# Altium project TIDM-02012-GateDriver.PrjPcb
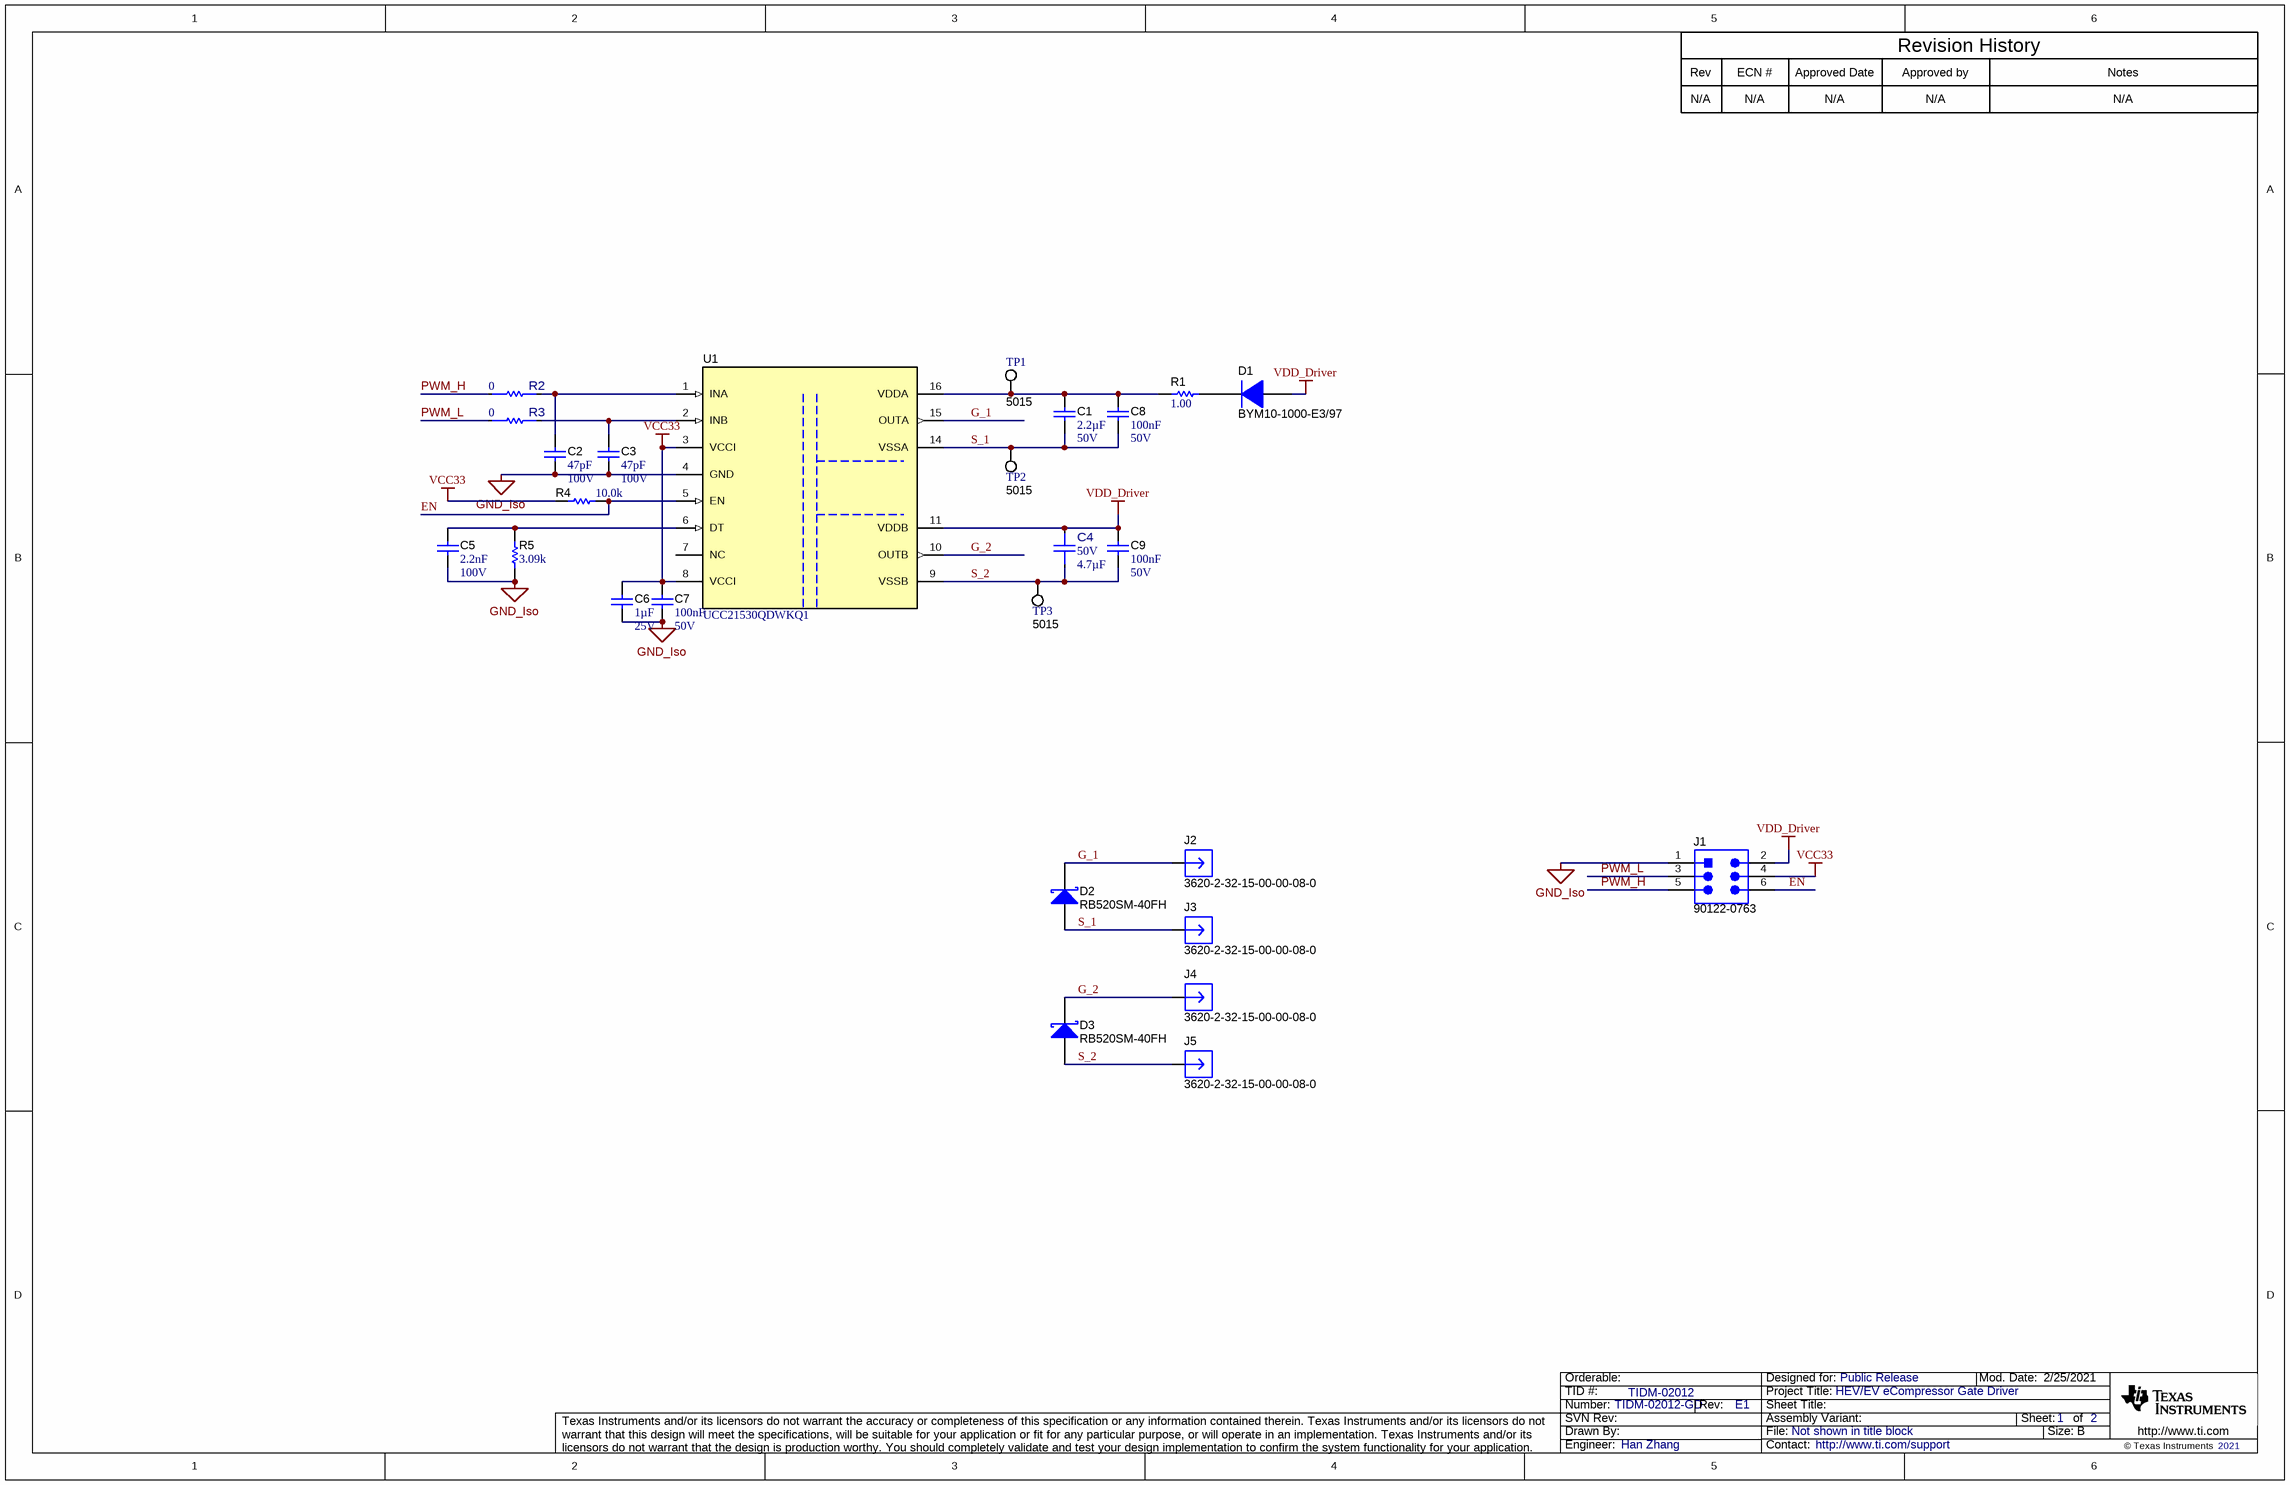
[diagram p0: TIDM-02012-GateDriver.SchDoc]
CopyrightYear: 2021; PCB_Layout: Han Zhang; PCB_Rev: E1; PRJ_Customer: Public Release; PRJ_Engineer: Han Zhang; PRJ_Number: TIDM-02012-GD; PRJ_Title: HEV/EV eCompressor Gate Driver; SCH_Rev: E1; TechSupport: http://www.ti.com/support; TID: TIDM-02012
2 sheets, 40 parts. Net scope: global (net labels, ports and power ports of the same name join across sheets).
Board file: TIDM-02012-GateDriver.PcbDoc
Sheets:
  TIDM-02012-GateDriver.SchDoc
  TIDM-02012-GateDriver_Hardware.SchDoc

## Sheet TIDM-02012-GateDriver.SchDoc
size 431 x 279 mm; Date: Not shown in title block; ApprovedBy: Not shown in title block; CheckedBy: Not shown in title block; Author: Not shown in title block; CompanyName: Not shown in title block; Engineer: Not shown in title block; Organization: Not shown in title block; Address1: Not shown in title block; Address2: Not shown in title block; Address3: Not shown in title block; Address4: Not shown in title block; DocumentNumber: 1; Revision: Use project parameter SCH_Rev; SheetNumber: 1; SheetTotal: 2; PageSetup: Record=PageOptions¦CenterHorizontal=True¦CenterVertical=True¦PrintScale=1.00¦XCorrection=1.00¦YCorrection=1.00¦PrintKind=0¦BorderSize=5000000¦LeftOffset=0¦BottomOffset=0¦Orientation=2¦PaperLength=1000¦PaperWidth=1000¦Scale=100¦PaperSource=15¦PrintQuality=600¦MediaType=1¦DitherType=10¦PaperKind=Letter¦PrintScaleMode=1

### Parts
C1  Cap_F: 2.2µF  VDC_V: 50V  [0805_HV]  (hidden comment: C2012X7R1H225M125AC)
C2  ValueDisplayed: 47pF  VDC_V: 100V  [0603]  (hidden comment: C0603C470J1GACAUTO)
C3  ValueDisplayed: 47pF  VDC_V: 100V  [0603]  (hidden comment: C0603C470J1GACAUTO)
C4  VDC_V: 50V  Cap_F: 4.7µF  [FP-C2012X7R1H475K125AC_0805-MFG]  (hidden comment: C2012X7R1H475K125AC)
C5  Cap_F: 2.2nF  VDC_V: 100V  [0603]  (hidden comment: CGA3E2X7R2A222K080AA)
C6  Cap_F: 1µF  VDC_V: 25V  [0603]  (hidden comment: CGA3E1X7R1E105M080AC)
C7  Cap_F: 100nF  VDC_V: 50V  [0603]  (hidden comment: C0603C104K5RACTU)
C8  Cap_F: 100nF  VDC_V: 50V  [0603]  (hidden comment: C0603C104K5RACTU)
C9  Cap_F: 100nF  VDC_V: 50V  [0603]  (hidden comment: C0603C104K5RACTU)
D1  BYM10-1000-E3/97  [DO-213AB]
D2  RB520SM-40FH  [SOD-523]
D3  RB520SM-40FH  [SOD-523]
J1  90122-0763  [Molex_90122-0763]
J2  3620-2-32-15-00-00-08-0  [Mill-Max_3620-2-32-xx-00-00-08-0]
J3  3620-2-32-15-00-00-08-0  [Mill-Max_3620-2-32-xx-00-00-08-0]
J4  3620-2-32-15-00-00-08-0  [Mill-Max_3620-2-32-xx-00-00-08-0]
J5  3620-2-32-15-00-00-08-0  [Mill-Max_3620-2-32-xx-00-00-08-0]
R1  ValueDisplayed: 1.00  [0805_HV]  (hidden comment: ERJ-6BQF1R0V)
R2  value 0  [FP-CRCW06030000Z0EBC_0603-MFG]  (hidden comment: CRCW06030000Z0EBC)
R3  value 0  [FP-CRCW06030000Z0EBC_0603-MFG]  (hidden comment: CRCW06030000Z0EBC)
R4  ValueDisplayed: 10.0k  [0603]  (hidden comment: RC0603FR-0710KL)
R5  ValueDisplayed: 3.09k  [0603]  (hidden comment: RC0603FR-073K09L)
TP1  5015  [Testpoint_Keystone_Miniature]
TP2  5015  [Testpoint_Keystone_Miniature]
TP3  5015  [Testpoint_Keystone_Miniature]
U1  UCC21530QDWKQ1  [DWK0014A]

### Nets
GND_Iso: C2.2 C3.2 C5.2 C6.2 C7.2 J1.1 R5.1 U1.4(GND)
VCC33: C6.1 C7.1 J1.4 R4.1 U1.3(VCCI) U1.8(VCCI)
VDD_Driver: C4.2 C9.2 D1.2(A) J1.2 U1.11(VDDB)
EN: J1.6 R4.2 U1.5(EN)
G_1: D2.1(K) J2.1 U1.15(OUTA)
G_2: D3.1(K) J4.1 U1.10(OUTB)
PWM_H: J1.5 R2.1
PWM_L: J1.3 R3.1
S_1: C1.2 C8.1 D2.2(A) J3.1 TP2.1 U1.14(VSSA)
S_2: C4.1 C9.1 D3.2(A) J5.1 TP3.1 U1.9(VSSB)
NetC1_1: C1.1 C8.2 R1.1 TP1.1 U1.16(VDDA)
NetC2_1: C2.1 R2.2 U1.1(INA)
NetC3_1: C3.1 R3.2 U1.2(INB)
NetC5_1: C5.1 R5.2 U1.6(DT)
NetD1_1: D1.1(K) R1.2

Not connected (* = marked no-connect by the designer): U1 7(NC)

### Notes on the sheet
- Rev
- N/A
- ECN #
- Approved Date
- Approved by
- Revision History
- Notes

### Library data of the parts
C1 = CMP-0007878-2: CAP, CERM, 2.2 uF, 50 V, +/- 20%, X7R, 0805; Manufacturer: TDK; TaMin_C: -55°C; Polarized: N; SizeAreaWB_mm2: 6.75; Value1: Unknown; U/M: EA; Value: 2.2uF; TaMax_C: 125°C; SizeZ_mm: 1.45; SizeX_mm: 2; SizeY_mm: 1.25; Cap_Case: 0805; SizeArea_mm2: 2.5; AEC Category: Q200
C2 C3 = CMP-0085572-1: CAP, CERM, 47 pF, 100 V,+/- 5%, C0G/NP0, AEC-Q200 Grade 1, 0603; Manufacturer: Kemet; TaMax_C: 125°C; AEC Category: Q200; AEC Grade: 1; TaMin_C: -55°C; SizeArea_mm2: 1.28; Value: 47pF; AEC Qualified: Y; Polarized: N; SizeX_mm: 1.6; U/M: EA; SizeY_mm: 0.8; SizeAreaWB_mm2: 4.68
C4 = CMP-0088943-1: 4.7µF ±10% 50V Ceramic Capacitor X7R 0805 (2012 Metric); Manufacturer: TDK; TempCo: 15%; AEC Qualified: No; ValueDisplayed: 4.7uF; SizeZ_mm: 1.5mm
C5 = CMP-0007085-4: CAP, CERM, 2200 pF, 100 V, +/- 10%, X7R, AEC-Q200 Grade 1, 0603; Manufacturer: TDK; TaMin_C: -55°C; ESR_ohm: 0.9239; Polarized: N; SizeAreaWB_mm2: 4.68; Value1: 0.923948 ohm; U/M: EA; Value: 2200pF; TaMax_C: 125°C; SizeZ_mm: 1; SizeX_mm: 1.6; SizeY_mm: 0.8; SizeArea_mm2: 1.28; AEC Qualified: Y; IRMS_A: 295.638mA; AEC Category: Q200
C6 = CMP-0082113-1: CAP, CERM, 1 µF, 25 V,+/- 20%, X7R, AEC-Q200 Grade 1, 0603; Manufacturer: TDK; SizeAreaWB_mm2: 4.68; SizeArea_mm2: 1.28; AEC Qualified: Y; AEC Category: Q200; Value: 1uF; TaMax_C: 125°C; SizeZ_mm: 1; Polarized: N; TaMin_C: -55°C; SizeY_mm: 0.8; U/M: EA; SizeX_mm: 1.6
C7-C9 = CMP-0006861-4: CAP, CERM, 0.1 uF, 50 V, +/- 10%, X7R, 0603; Manufacturer: Kemet; TaMin_C: -55°C; Polarized: N; SizeAreaWB_mm2: 4.68; Value1: Unknown; U/M: EA; Value: 0.1uF; TaMax_C: 125°C; SizeZ_mm: 1; SizeX_mm: 1.6; SizeY_mm: 0.8; SizeArea_mm2: 1.28; AEC Category: Q200
D1 = CMP-0076899-2: Diode, P-N, 1000 V, 1 A, DO-213AB; Manufacturer: Vishay-Semiconductor; Vr_V: 1kV; SizeZ_mm: 2.67; Green_REACh: Incomplete; Value: 1000V; RJC_CperW: 75.0; TJmax_C: 175°C; Green_Lifecycle: Not Set; SizeX_mm: 4.95; Io_A: 1A; SizeY_mm: 2.54; Value2: 1.2V; AEC Category: Q101; SizeAreaWB_mm2: 21.063; SizeArea_mm2: 12.573
D2 D3 = CMP-0077062-3: Diode, Schottky, 45 V, 0.2 A, AEC-Q101, SOD-523; Manufacturer: Rohm; TJmax_C: 150°C; SizeAreaWB_mm2: 5.13; Vr_V: 45V; SizeZ_mm: 0.65; SizeArea_mm2: 1.53; SizeY_mm: 0.9; Vf_V: 550mV; Value2: 0.55V; SizeX_mm: 1.7; Value: 45V; Green_REACh: Incomplete; AEC Category: Q101; Value1: 0.2A; Green_Lifecycle: Not Set; Io_A: 200mA; AEC Qualified: Y
J1 = CMP-0077741-2: Header, 2.54mm, 3x2, Gold, R/A, TH; Manufacturer: Molex; Pitch_mm: 2.54; Gender: Male; Cert_UL: Y; Current_A: 3A; Voltage_V: 350V; Shrouded: N; Row_Count: 2
J2-J5 = CMP-0055044-1: Manufacturer: Mill-Max; CNHeader: FALSE; Gender: Male; CompType: PCB Pin; Row_Count: 1; ContactFinish: Gold
R1 = CMP-0074786-1: RES, 1.00, 1%, 0.333 W, AEC-Q200 Grade 1, 0805; Manufacturer: Panasonic; Power_W: 333mW; TempCo: 200 ppm/C; Value_Code: 1R00; U/M: EA; Value: 1.00; EIA_Code: E96; Res_ohm: 1; SizeX_mm: 2.0; SizeY_mm: 1.25; SizeZ_mm: 1.45; Value2: 0.333W; SizeArea_mm2: 2.5; AEC Qualified: Y; AEC Category: Q200
R2 R3 = CMP-0093667-1: CRCW Thick Film Commodity Chip Resistor Jumper 0603 Size 0 Ohm 0.1 W 2-Pin SMD Paper T/R; Manufacturer: Vishay; SizeZ_mm: 0.55mm; VDC_V: 75V; Power_W: 100mW; AEC Qualified: No
R4 = CMP-0022746-5: RES, 10.0 k, 1%, 0.1 W, 0603; Manufacturer: Yageo; Power_W: 100mW; TempCo: 100 ppm/C; Value_Code: 10k0; Value: 10.0k; EIA_Code: E96; Res_ohm: 10k; SizeX_mm: 1.6; SizeY_mm: 0.8; SizeZ_mm: 1; Value2: 0.1W; SizeArea_mm2: 1.28; AEC Qualified: N; VDC_V: 75V; AEC Category: Q200; SizeAreaWB_mm2: 4.68
R5 = CMP-0023077-5: RES, 3.09 k, 1%, 0.1 W, 0603; Manufacturer: Yageo; Power_W: 100mW; TempCo: 100 ppm/C; Value_Code: 3k09; Value: 3.09k; EIA_Code: E96; SizeX_mm: 1.6; SizeY_mm: 0.8; SizeZ_mm: 1; Value2: 0.1W; SizeArea_mm2: 1.28; AEC Qualified: N; VDC_V: 75V; AEC Category: Q200; SizeAreaWB_mm2: 4.68
TP1-TP3 = CMP-0055152-1: Test Point, Miniature, SMT; Manufacturer: Keystone; CNHeader: FALSE; Green_Lifecycle: Active; Green_REACh: Passed; CT: TRUE
U1 = CMP-0083996-1: 4-A, 6-A, 5.7-kVRMS Isolated Dual-Channel Gate Driver with Enable, DWK0014A (SOIC-14); Alternate PartNumber: UCC21530QDWKRQ1; Alternate Manufacturer: Texas Instruments; SizeAreaWB_mm2: 151.29; SizeZ_mm: 2.65; SizeX_mm: 10.3; SizeArea_mm2: 106.09; CompType: IC; AEC Qualified: Y; AEC Category: Q200

## Sheet TIDM-02012-GateDriver_Hardware.SchDoc
size 431 x 279 mm; Date: Not shown in title block; ApprovedBy: Not shown in title block; CheckedBy: Not shown in title block; Author: Not shown in title block; CompanyName: Not shown in title block; Engineer: Not shown in title block; Organization: Not shown in title block; Address1: Not shown in title block; Address2: Not shown in title block; Address3: Not shown in title block; Address4: Not shown in title block; DocumentNumber: 3; Revision: Use project parameter SCH_Rev; SheetNumber: 2; SheetTotal: 2; PageSetup: Record=PageOptions¦CenterHorizontal=True¦CenterVertical=True¦PrintScale=1.00¦XCorrection=1.00¦YCorrection=1.00¦PrintKind=0¦BorderSize=5000000¦LeftOffset=0¦BottomOffset=0¦Orientation=2¦PaperLength=1000¦PaperWidth=1000¦Scale=100¦PaperSource=15¦PrintQuality=600¦MediaType=1¦DitherType=10¦PaperKind=Letter¦PrintScaleMode=1
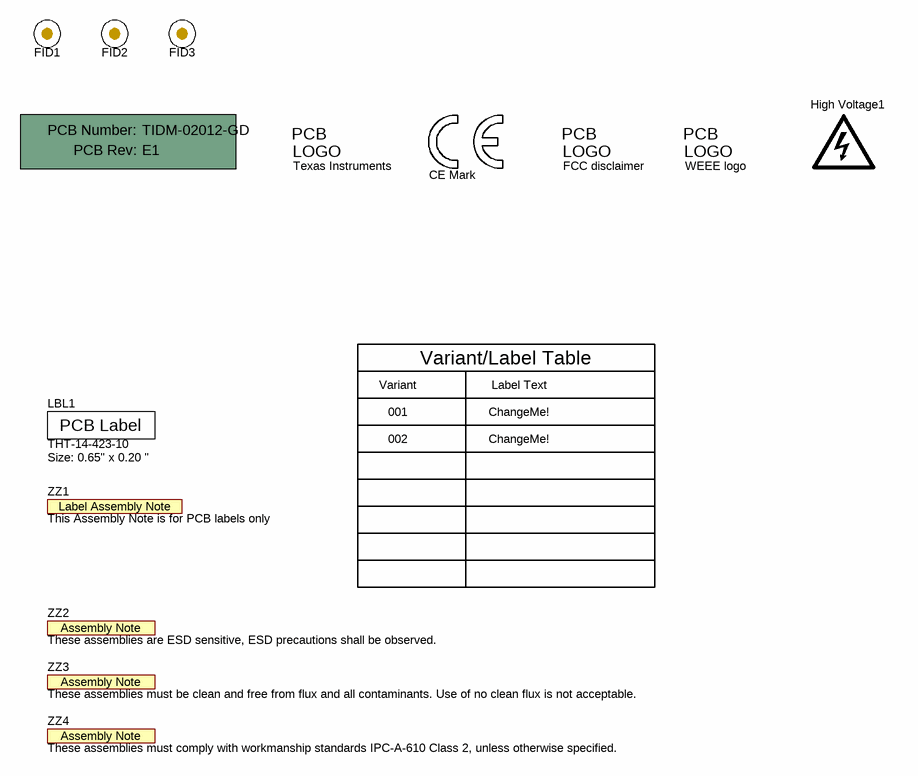
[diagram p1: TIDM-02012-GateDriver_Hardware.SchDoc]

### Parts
!PCB  Printed Circuit Board  (value not drawn)  (mechanical)
FID1  Fiducial  [Fiducial10-20]  (value not drawn)
FID2  Fiducial  [Fiducial10-20]  (value not drawn)
FID3  Fiducial  [Fiducial10-20]  (value not drawn)
High_Voltage1  DANGER HIGH VOLTAGE  [IEC_HighVoltage_Medium]  (value not drawn)  (no BOM)
LBL1  THT-14-423-10  Note: Size: 0.65" x 0.20 "  [Label_650x200]
Logo1  Texas Instruments  [TI_Stacked_Overlay_Small]  (no BOM)
Logo2  CE Mark  [CE_Mark_5mm]  (no BOM)
Logo3  FCC disclaimer  [FCC_disclaimer]  (no BOM)
Logo4  WEEE logo  [WEEE_Minimum]  (no BOM)
ZZ1  This Assembly Note is for PCB labels only  [AssemblyNoteLabel]  (no BOM)
ZZ2  These assemblies are ESD sensitive, ESD precautions shall be observed.  [AssemblyNote]  (no BOM)
ZZ3  These assemblies must be clean and free from flux and all contaminants. Use of no clean flux is not acceptable.  [AssemblyNote]  (no BOM)
ZZ4  These assemblies must comply with workmanship standards IPC-A-610 Class 2, unless otherwise specified.  [AssemblyNote]  (no BOM)

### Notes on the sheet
- Variant
- Variant/Label Table
- Label Text
- 001
- 002
- ChangeMe!

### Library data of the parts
!PCB = CMP-0003618-2: Manufacturer: Any; PartNumber: TIDM-02012-GD
FID1-FID3 = CMP-0077181-1: Fiducial mark.  There is nothing to buy or mount.
High_Voltage1 = CMP-0074835-1: IEC 61010-1 High Voltage Warning; SymbolCreator: a0412235
LBL1 = CMP-0003625-1: Thermal Transfer Printable Labels, 0.650" W x 0.200" H - 10,000 per roll; Manufacturer: Brady; CompType: Label
Logo1 = CMP-0074838-1: Texas Instrument Corporate Signature; SymbolCreator: a0412235; Lib Reference: TI_Logo; Library Reference: Logo
Logo2 = CMP-0074844-1: SymbolCreator: a0412235
Logo3 = CMP-0074847-1: FCC_disclaimer; Library Reference: Logo
Logo4 = CMP-0074769-1
ZZ1 = CMP-0003616-3
ZZ2 = CMP-0077236-1
ZZ3 = CMP-0077237-1
ZZ4 = CMP-0077238-1

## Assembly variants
001: not fitted FID1 FID2 FID3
